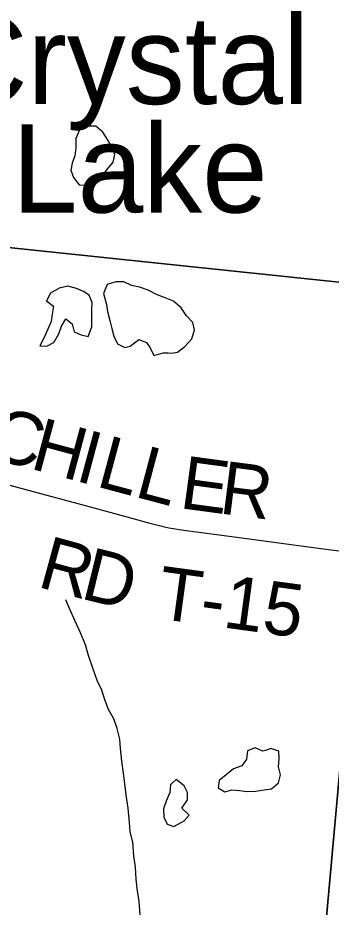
# Model space of a CAD drawing. Extents: x 0 to 680, y 0 to 440.
# Drawn here: x 168.79 to 174.06, y 273.01 to 287.97 of the extents above; entities that cross this region are included whole.
import ezdxf

# ---------------------------------------------------------------- set-up
doc = ezdxf.new("R2010")
doc.units = 0
for name, color, linetype in [('GM_X_Minor_Lake', 7, 'Continuous'), ('GM_X_Minor_Lake_Text', 7, 'Continuous'), ('GM_X_Minor_River', 7, 'Continuous'), ('GM_X_Section', 7, 'Continuous'), ('GM_X_Township_Road', 7, 'Continuous'), ('GM_X_Township_Road_Text', 7, 'Continuous')]:
    doc.layers.add(name, color=color, linetype=linetype)

msp = doc.modelspace()

# ---------------------------------------------------------------- linework, layer by layer
at = {"layer": 'GM_X_Minor_Lake'}
for points in [[(170.425, 285.667), (170.379, 285.781), (170.303, 285.918), (170.222, 286.044), (170.104, 286.141), (169.974, 286.142), (169.836, 286.09), (169.769, 285.937), (169.768, 285.843)], [(169.768, 285.843), (169.767, 285.776), (169.754, 285.646), (169.705, 285.522), (169.685, 285.403), (169.731, 285.278), (169.825, 285.158), (169.949, 285.15), (170.074, 285.161), (170.194, 285.284), (170.291, 285.407), (170.399, 285.537), (170.425, 285.667)], [(169.992, 283.302), (169.897, 283.363), (169.779, 283.412), (169.637, 283.455), (169.489, 283.421), (169.345, 283.334), (169.278, 283.204), (169.396, 283.114), (169.37, 282.983), (169.357, 282.859), (169.296, 282.729), (169.235, 282.587), (169.162, 282.451), (169.28, 282.444), (169.4, 282.507), (169.485, 282.649), (169.528, 282.779), (169.601, 282.903), (169.707, 282.819), (169.741, 282.687), (169.791, 282.664)], [(171.321, 282.329), (171.38, 282.328), (171.476, 282.345), (171.601, 282.438), (171.722, 282.567), (171.765, 282.721), (171.737, 282.841), (171.632, 282.955), (171.538, 283.087), (171.409, 283.201), (171.273, 283.256), (171.126, 283.312), (170.984, 283.385), (170.842, 283.434), (170.706, 283.465), (170.576, 283.526), (170.44, 283.528), (170.297, 283.482), (170.235, 283.329)], [(169.791, 282.664), (169.859, 282.632), (169.977, 282.607), (170.038, 282.767), (170.04, 282.921), (170.036, 283.052), (170.044, 283.177), (169.992, 283.302)], [(170.235, 283.329), (170.286, 283.144), (170.303, 283.025), (170.342, 282.876), (170.376, 282.739), (170.41, 282.614), (170.468, 282.482), (170.592, 282.421), (170.681, 282.444), (170.831, 282.555), (170.955, 282.506), (171.019, 282.416), (171.083, 282.284), (171.238, 282.33), (171.321, 282.329)], [(172.957, 275.646), (172.911, 275.631), (172.782, 275.692), (172.656, 275.64), (172.637, 275.498), (172.558, 275.386), (172.421, 275.334), (172.295, 275.235), (172.181, 275.141), (172.162, 275.017), (172.274, 274.95)], [(172.274, 274.95), (172.393, 274.984), (172.523, 274.97), (172.648, 274.957), (172.79, 274.961), (172.933, 274.983), (173.058, 274.999), (173.178, 275.099), (173.209, 275.235), (173.175, 275.372), (173.189, 275.503), (173.184, 275.633), (173.048, 275.677), (172.957, 275.646)], [(171.396, 275.1), (171.361, 275.068), (171.348, 274.938), (171.286, 274.79), (171.243, 274.666), (171.247, 274.523), (171.305, 274.404), (171.418, 274.366)], [(171.418, 274.366), (171.591, 274.459), (171.675, 274.559), (171.552, 274.674), (171.649, 274.815), (171.644, 274.94), (171.592, 275.053), (171.457, 275.156), (171.396, 275.1)]]:
    msp.add_lwpolyline(points, dxfattribs=at)
at = {"layer": 'GM_X_Minor_River'}
msp.add_lwpolyline([(170.853, 272.882), (170.832, 273.108), (170.799, 273.323), (170.783, 273.483), (170.774, 273.685), (170.747, 273.876), (170.726, 274.102), (170.68, 274.275), (170.67, 274.435), (170.65, 274.673), (170.617, 274.899), (170.595, 275.084), (170.568, 275.262), (170.541, 275.465), (170.52, 275.679), (170.51, 275.833), (170.465, 276.012), (170.407, 276.179), (170.32, 276.335), (170.257, 276.496), (170.206, 276.657), (170.13, 276.819), (170.05, 277.045), (169.981, 277.242), (169.93, 277.421), (169.85, 277.624), (169.757, 277.821), (169.665, 278.03), (169.601, 278.18)], dxfattribs=at)
at = {"layer": 'GM_X_Section'}
for points in [[(160.808, 300.853), (176.459, 299.296), (174.94, 283.442), (159.118, 285.103)], [(159.118, 285.103), (174.94, 283.442), (173.525, 267.764), (158.298, 269.195), (157.8, 269.245)], [(174.94, 283.442), (190.555, 281.787), (188.936, 266.093), (173.956, 267.691), (173.525, 267.764)]]:
    msp.add_lwpolyline(points, close=True, dxfattribs=at)
at = {"layer": 'GM_X_Township_Road'}
msp.add_lwpolyline([(166.773, 280.607), (166.855, 280.587), (167.186, 280.502), (169.112, 279.981), (169.803, 279.799), (170.463, 279.621), (170.748, 279.54), (170.991, 279.475), (171.262, 279.406), (171.335, 279.39), (171.411, 279.375), (171.471, 279.365), (171.625, 279.342), (171.797, 279.32), (172.31, 279.254), (173.971, 279.028), (174.51, 278.96)], dxfattribs=at)

# ---------------------------------------------------------------- texts
at = {"layer": 'GM_X_Minor_Lake_Text'}
for s, p in [('Crystal', (167.527, 286.515)), ('Lake', (168.697, 284.69))]:
    msp.add_text(s, height=1.4823, rotation=0.0085, dxfattribs=at).set_placement(p)
at = {"layer": 'GM_X_Township_Road_Text'}
for s, height, rotation, p in [('C', 0.889, 344.928, (168.274, 280.581)), ('H', 0.889, 344.926, (168.979, 280.391)), ('I', 0.889, 344.928, (169.735, 280.187)), ('L', 0.889, 344.9286, (170.088, 280.092)), ('L', 0.889, 345.0834, (170.733, 279.919)), ('E', 0.889, 352.3362, (171.496, 279.723)), ('R', 0.889, 352.685, (172.161, 279.634)), ('R', 0.889, 344.7795, (169.101, 278.403)), ('D', 0.889, 346.1037, (169.827, 278.206)), ('T-15', 0.8894, 352.2656, (171.109, 277.868))]:
    msp.add_text(s, height=height, rotation=rotation, dxfattribs=at).set_placement(p)

doc.saveas('drawing.dxf')
